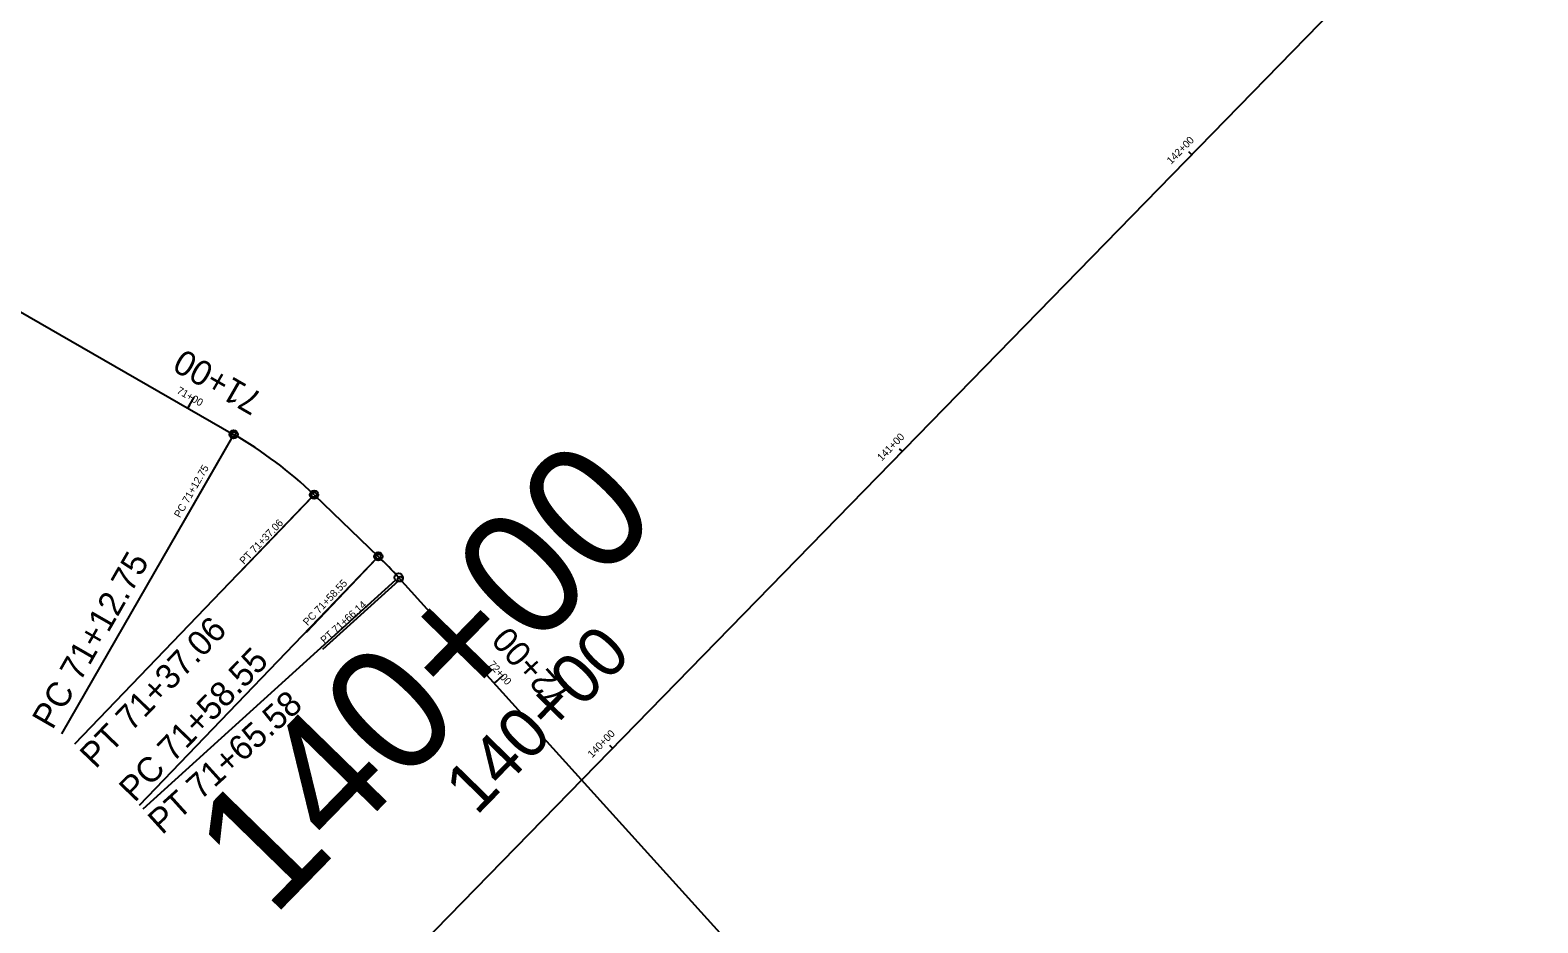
# Model space of a CAD drawing. Extents: x 2252491 to 2257126, y 13788370 to 13792743.
# Drawn here: x 2255321.9 to 2255685.6, y 13791291.8 to 13791507.1 of the extents above; entities that cross this region are included whole.
import ezdxf

# ---------------------------------------------------------------- set-up
doc = ezdxf.new("R2010")
doc.units = 0
for name, color, linetype in [('D_ALIGN_1', 7, 'Continuous'), ('D_ALIGN_ANNO_1', 7, 'Continuous'), ('D_ALIGN_ANNO_200_drn', 7, 'Continuous'), ('D_ALIGN_ANNO_DOVE_CROSSING', 7, 'Continuous'), ('D_ALIGN_ANNO_DOVE_CROSSING_30', 7, 'Continuous'), ('D_ALIGN_ANNO_DRN_300', 7, 'Continuous'), ('D_ALIGN_DOVE_CROSSING', 7, 'Continuous')]:
    doc.layers.add(name, color=color, linetype=linetype)

msp = doc.modelspace()

# ---------------------------------------------------------------- linework, layer by layer
at = {"layer": 'D_ALIGN_1'}
msp.add_line((2255392.67, 13791262.46), (2255685.62, 13791562.66), dxfattribs=at)
at = {"layer": 'D_ALIGN_ANNO_1'}
for p, q in [((2255602.1, 13791477.08), (2255601.46, 13791477.71)), ((2255532.26, 13791405.51), (2255531.62, 13791406.14)), ((2255462.42, 13791333.94), (2255461.77, 13791334.57))]:
    msp.add_line(p, q, dxfattribs=at)
at = {"layer": 'D_ALIGN_ANNO_DOVE_CROSSING'}
for p, q in [((2255359.98, 13791415.94), (2255361.47, 13791418.54)), ((2255370.53, 13791408.71), (2255329.51, 13791337.41)), ((2255389.73, 13791394.31), (2255332.65, 13791334.87)), ((2255405.23, 13791379.42), (2255348.26, 13791320.09)), ((2255410.08, 13791374.43), (2255349.08, 13791319.24)), ((2255433.91, 13791349.57), (2255436.14, 13791351.59))]:
    msp.add_line(p, q, dxfattribs=at)
for centre in [(2255371.02, 13791409.58), (2255390.42, 13791395.03), (2255405.92, 13791380.15), (2255410.82, 13791375.1)]:
    msp.add_circle(centre, 1, dxfattribs=at)
at = {"layer": 'D_ALIGN_ANNO_DOVE_CROSSING_30'}
for p, q in [((2255359.98, 13791415.94), (2255360.42, 13791416.72)), ((2255370.73, 13791409.06), (2255358.42, 13791387.67)), ((2255390.01, 13791394.6), (2255372.88, 13791376.76)), ((2255405.48, 13791379.68), (2255388.49, 13791361.78)), ((2255410.75, 13791374.28), (2255392.46, 13791357.73)), ((2255433.91, 13791349.57), (2255434.58, 13791350.18))]:
    msp.add_line(p, q, dxfattribs=at)
for centre in [(2255371.02, 13791409.58), (2255390.42, 13791395.03), (2255405.9, 13791380.12), (2255411.2, 13791374.68)]:
    msp.add_circle(centre, 0.6, dxfattribs=at)
at = {"layer": 'D_ALIGN_DOVE_CROSSING'}
for p, q in [((2255273.29, 13791465.8), (2255371.02, 13791409.58)), ((2255390.42, 13791395.03), (2255405.92, 13791380.15)), ((2255410.82, 13791375.1), (2255578.91, 13791189.28))]:
    msp.add_line(p, q, dxfattribs=at)
for centre, start, end in [((2255321.16, 13791322.9), 46.1633, 60.091), ((2255336.66, 13791308.01), 42.1313, 46.1633)]:
    msp.add_arc(centre, 100, start, end, dxfattribs=at)

# ---------------------------------------------------------------- texts
at = {"layer": 'D_ALIGN_ANNO_1'}
for s, p in [('142+00', (2255597.18, 13791474.61)), ('141+00', (2255527.34, 13791403.04)), ('140+00', (2255457.49, 13791331.47))]:
    msp.add_text(s, height=1.8, rotation=45.7003, dxfattribs=at).set_placement(p)
at = {"layer": 'D_ALIGN_ANNO_200_drn'}
msp.add_text('140+00', height=12, rotation=45.7003, dxfattribs=at).set_placement((2255429.59, 13791317.47))
at = {"layer": 'D_ALIGN_ANNO_DOVE_CROSSING'}
for s, rotation, p in [('71+00', 150.091, (2255378.43, 13791419.17)), ('PC 71+12.75', 60.091, (2255327.31, 13791338.15)), ('PT 71+37.06', 46.1633, (2255337.71, 13791328.75)), ('72+00', 132.1313, (2255452.46, 13791346.96)), ('PC 71+58.55', 46.1633, (2255347.15, 13791320.65)), ('PT 71+65.58', 42.1313, (2255353.76, 13791312.86))]:
    msp.add_text(s, height=6, rotation=rotation, dxfattribs=at).set_placement(p)
at = {"layer": 'D_ALIGN_ANNO_DOVE_CROSSING_30'}
for s, rotation, p in [('71+00', 330.091, (2255357.13, 13791419.65)), ('PC 71+12.75', 60.091, (2255358.07, 13791389.34)), ('PT 71+37.06', 46.1633, (2255373.52, 13791378.1)), ('PC 71+58.55', 46.4825, (2255388.86, 13791363.32)), ('PT 71+66.14', 42.1313, (2255392.95, 13791359)), ('72+00', 312.1313, (2255432.35, 13791353.98))]:
    msp.add_text(s, height=1.8, rotation=rotation, dxfattribs=at).set_placement(p)
at = {"layer": 'D_ALIGN_ANNO_DRN_300'}
msp.add_text('140+00', height=30, rotation=45.7003, dxfattribs=at).set_placement((2255380.34, 13791292.78))

doc.saveas('drawing.dxf')
